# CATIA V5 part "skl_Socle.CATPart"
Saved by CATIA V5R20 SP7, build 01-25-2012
Part number: skl_Socle
Publications: "Axe_SocleEquerre7", "Axe_SocleRoue8", "Axe_SocleEquerre6", "Axe_SocleLevier1", "Plan.1", "Point.2", "Point.21", "Point.3", "Point.4"
Bounding box of the stored display mesh (mm): x 0 to 20, y -38.041 to 38.041, z 68 to 152
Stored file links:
  J:\ACHTUNG2\skl_Socle.CATPart
  J:\cmilovidofIAO\skl_IAO.CATProduct
  J:\ACHTUNG2\skl_IAO2.CATProduct
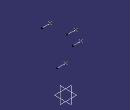
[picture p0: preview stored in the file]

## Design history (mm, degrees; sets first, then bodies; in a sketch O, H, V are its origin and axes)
Set1
  Plane1: linked copy from another document
  Point1 to Point3: linked copy from another document
  Point4 "Point.2": linked copy from another document
Body1 (main body)
  Line1: type Normal, RefPoint Point1, RefSkin Plane1, Start 0, End 20
  Line2: type Normal, RefPoint Point2, RefSkin Plane1, Start 0, End 20
  Line3: type Normal, RefPoint Point3, RefSkin Plane1, Start 0, End 20
  Line4: type Normal, RefPoint Point4, RefSkin Plane1, Start 0, End 20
